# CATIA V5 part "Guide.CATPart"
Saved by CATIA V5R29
Part number: Guide_01
Source: Unknown
Bounding box of the stored display mesh (mm): x 0 to 200, y -20 to 20, z 730 to 1000
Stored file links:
  C:\가치같이\SmartFactory_BoxErectorConveyor\Boxing(under)\Guide.CATPart
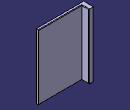
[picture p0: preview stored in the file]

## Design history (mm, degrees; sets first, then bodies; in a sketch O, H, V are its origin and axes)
Body1 (main body)
  Solid1 "PartBody": solid without history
